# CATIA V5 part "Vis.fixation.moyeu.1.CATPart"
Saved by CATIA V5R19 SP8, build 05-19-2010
Part number: Vis.fixation.moyeu.1
Bounding box of the stored display mesh (mm): x -24 to -18, y -1.5 to 1.5, z -1.5 to 1.5
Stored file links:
  G:\EU_thinkMotion\CFAO_2010\MMS_groupe3\MMS_groupe3\jbonnamy\jbonnamy_cfao\Vis.fixation.moyeu.1.CATPart
  C:\Users\Micheline\Desktop\projet CFAO\Nouveau dossier\temp\Nouveau dossier\Vis.fixation.CATPart
  G:\EU_thinkMotion\CFAO_2010\MMS_groupe3\MMS_groupe3\jbonnamy\jbonnamy_cfao\jbonnamy_suspension.arriere.directionnelle.CATProduct
  G:\EU_thinkMotion\CFAO_2010\MMS_groupe3\MMS_groupe3\jbonnamy\jbonnamy_cfao\Moyeu.CATPart
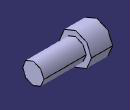
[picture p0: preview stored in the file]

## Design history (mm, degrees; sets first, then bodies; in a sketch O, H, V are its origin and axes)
External parameters (linked from other documents)
  External.Epaisseur.support.10 = 1.5 mm
  External.Diametre.vis.fixation = 2 mm
Set1
  DatumSurface1: linked copy from another document
Body1 (main body)
  Sketch1 on DatumSurface1, origin (-22, 0, 0), H (0, -1, 0), V (0, 0, 1)
    circle A1 centre (0, 0) radius 1
    radius A1 = 1 {= External.Diametre.vis.fixation /2}
  Pad1: profile Sketch1, direction (1, 0, 0), length 4 {= 2*External.Epaisseur.support.10 +1mm}
  Sketch2 on DatumSurface1, origin (-22, 0, 0), H (0, -1, 0), V (0, 0, 1)
    circle A1 centre (0, 0) radius 1.5
    radius A1 = 1.5 {= 3*External.Diametre.vis.fixation /4}
  Pad2: profile Sketch2, direction (-1, 0, 0), length 2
